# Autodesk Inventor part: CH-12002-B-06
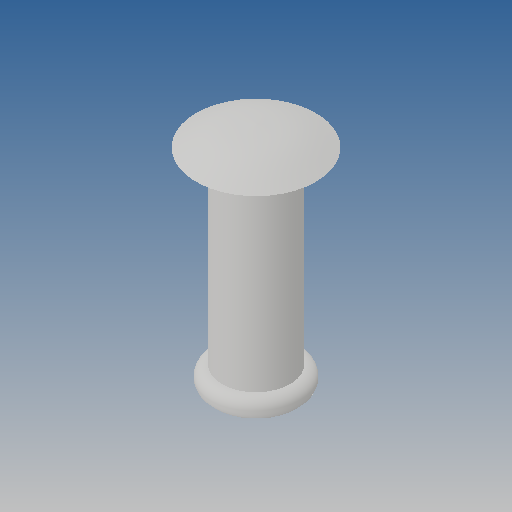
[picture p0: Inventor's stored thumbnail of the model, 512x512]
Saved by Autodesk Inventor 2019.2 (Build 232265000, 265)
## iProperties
Created: 2012-09
Part Number: CH-12002-B-06
Material: Ogólny
Document SubType Name: Modeling
Designer: CADENGINEERING4
Density: 1 g/cm^3
Appearance: Domyślna
Author: CADENGINEERING4
Revision Number: ÈÎºÎ
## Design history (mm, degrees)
feature "Ðý×ª1"
node "Bryła1"
